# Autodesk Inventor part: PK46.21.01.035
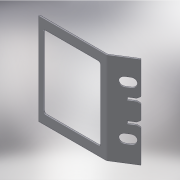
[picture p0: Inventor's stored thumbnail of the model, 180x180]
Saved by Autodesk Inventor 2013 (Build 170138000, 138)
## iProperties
Created: 2005-04
Part Number: PK46.21.01.035
Material: Steel, Mild
Document SubType Name: Обычные детали
Designer: salex
Manufacturer: Standard
Standards Organization: Custom
Density: 7.86 g/cm^3
Sheet Metal Rule: Default
Author: salex
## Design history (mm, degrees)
node "ФлнОтгиб1"
sketch "Эскиз2"
  geometry: L1 (0, 800)-(0, 0) reference; L2 (-206.772, 800)-(0, 800) reference; L3 (-60, 655)-(-100, 655); L4 (-100, 575)-(-60, 575); L5 (-85, 478)-(0, 478); L6 (0, 478)-(0, 502); L7 (0, 502)-(-85, 502); L8 (-85, 502)-(-85, 478); L9 (0, 400)-(-88.452, 400); L10 (-85, 322)-(0, 322); L11 (0, 322)-(0, 298); L12 (-85, 298)-(-85, 322); L13 (-100, 225)-(-60, 225); L14 (0, 298)-(-85, 298); L15 (-60, 145)-(-100, 145); A1 r 40 centre (-100, 615) between (-100, 655) and (-100, 575); A2 r 40 centre (-60, 615) between (-60, 575) and (-60, 655); A3 r 40 centre (-100, 185) between (-100, 225) and (-100, 145); A4 r 40 centre (-60, 185) between (-60, 145) and (-60, 225)
  constraints: 26 end point, 10 symmetric about line, 8 point on circle, 4 centre point, 4 parallel, 4 tangent, 2 perpendicular, 1 horizontal, 1 midpoint, 1 point on line, 2 other
  dimensions: "d10" = 298 distance between parallel lines of L7 L2; "d11" = 24 distance between parallel lines of L7 L5; "d12" = 85 distance between parallel lines of L1 L8; "d13" = 145 distance between parallel lines of L2 L3; "d14" = 40 distance of A2.centre A1.centre; "d15" = 40 radius of A1; "d16" = 60 distance from line of A2.centre L1
extrude "Выдавливание1" cut sketch "Эскиз2" stored distance "d17" = 10; taper "d18" = 0 deg
feature "Угловая фаска1" dims "d19" = 15, "d20" = 25, angle "d21" = 45 deg
sketch "Эскиз3"
  geometry: L1 (0, 800)-(584.242, 800) reference; L2 (0, 800)-(0, 0) reference; L3 (0, 0)-(584.242, 0) reference; L4 (40, 720)-(540, 720); L5 (540, 720)-(540, 80); L6 (540, 80)-(40, 80); L7 (584.242, 0)-(584.242, 800) reference; L8 (40, 720)-(40, 80)
  constraints: 8 end point, 4 parallel, 1 perpendicular
  dimensions: "d23" = 80 distance between parallel lines of L4 L1; "d24" = 540 distance between parallel lines of L5 L2; "d34" = 40 distance between parallel lines of L8 L2; "d35" = 640 distance of L4.start L6.end
extrude "Выдавливание2" cut sketch "Эскиз3" stored distance "d26" = 10; taper "d27" = 0 deg
fillet "Сопряжение1" dims "d33" = 20
fillet "Сопряжение2" dims "d36" = 20
chamfer "Фаска1" distance "d37" = 25 (= d20); stored, may be unused: second distance "d38" = 15 (= d19), angle "d39" = 45 deg
chamfer "Фаска2" distance "d40" = 25 (= d20); stored, may be unused: second distance "d41" = 15 (= d19), angle "d42" = 45 deg
chamfer "Фаска3" distance "d43" = 25 (= d20); stored, may be unused: second distance "d44" = 15 (= d19), angle "d45" = 45 deg
body "Solid1"
sketch "Эскиз1"
  geometry: L1 (0, 0)-(590, 0); L2 (590, 0)-(770, 113)
  constraints: 4 end point, 1 horizontal, 1 other
  dimensions: "d0" = 590 distance of L1.start L1.end; "d1" = 113 distance from line of L2.end L1; "d2" = 770 horizontal distance of L1.start L2.end
feature "Плакирование1" dims "d3" = 800, "d4" = 10 (= BendReliefWidth), "d6" = 20 (= MinimumRemnant), "d8" = 20 (= BendRadius), "d9" = 10, "Thickness" = 10
feature "Изгиб1" dims "d4" = 10 (= BendReliefWidth), "d5" = 5 (= BendReliefDepth), "d6" = 20 (= MinimumRemnant), "d7" = 20 (= BendRadius), "d8" = 20 (= BendRadius), "d9" = 10, "SeamGap" = 0.01, "Thickness" = 10
other parameters: "BendRadius" = 20, "BendReliefDepth" = 5 (= 0.5 x Thickness)
